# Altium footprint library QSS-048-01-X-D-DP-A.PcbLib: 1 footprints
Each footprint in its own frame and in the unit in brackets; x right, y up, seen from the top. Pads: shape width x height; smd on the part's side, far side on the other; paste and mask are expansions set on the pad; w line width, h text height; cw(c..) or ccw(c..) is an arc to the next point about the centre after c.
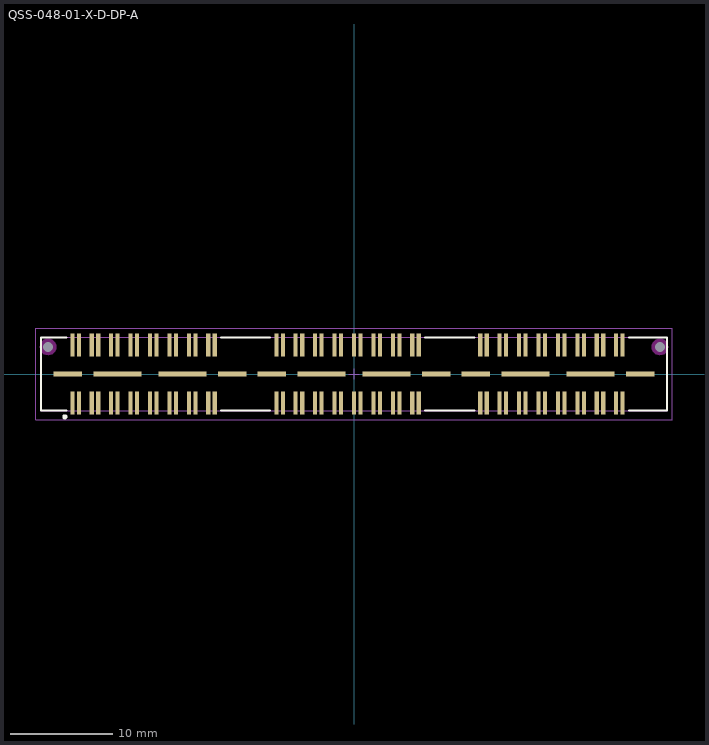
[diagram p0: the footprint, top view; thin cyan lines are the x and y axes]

## QSS-048-01-X-D-DP-A [mm] "0.635mm pitch, high speed socket; differential pair array"
height 3.43
pads (110):
  rect 0.4x2.25 smd mask+0: 1(-27.62,-2.865) 2(-27.62,2.865) 3(-26.98,-2.865) 4(-26.98,2.865) 5(-25.716,-2.865) 6(-25.716,2.865) 7(-25.076,-2.865) 8(-25.076,2.865) 9(-23.812,-2.865) 10(-23.812,2.865) 11(-23.172,-2.865) 12(-23.172,2.865) 13(-21.908,-2.865) 14(-21.908,2.865) 15(-21.268,-2.865) 16(-21.268,2.865) 17(-20.004,-2.865) 18(-20.004,2.865) 19(-19.364,-2.865) 20(-19.364,2.865) 21(-18.1,-2.865) 22(-18.1,2.865) 23(-17.46,-2.865) 24(-17.46,2.865) 25(-16.196,-2.865) 26(-16.196,2.865) 27(-15.556,-2.865) 28(-15.556,2.865) 29(-14.292,-2.865) 30(-14.292,2.865) 31(-13.652,-2.865) 32(-13.652,2.865) 33(-7.62,-2.865) 34(-7.62,2.865) 35(-6.98,-2.865) 36(-6.98,2.865) 37(-5.716,-2.865) 38(-5.716,2.865) 39(-5.076,-2.865) 40(-5.076,2.865) 41(-3.812,-2.865) 42(-3.812,2.865) 43(-3.172,-2.865) 44(-3.172,2.865) 45(-1.908,-2.865) 46(-1.908,2.865) 47(-1.268,-2.865) 48(-1.268,2.865) 49(-0.004,-2.865) 50(-0.004,2.865) 51(0.636,-2.865) 52(0.636,2.865) 53(1.9,-2.865) 54(1.9,2.865) 55(2.54,-2.865) 56(2.54,2.865) 57(3.804,-2.865) 58(3.804,2.865) 59(4.444,-2.865) 60(4.444,2.865) 61(5.708,-2.865) 62(5.708,2.865) 63(6.348,-2.865) 64(6.348,2.865) 65(12.38,-2.865) 66(12.38,2.865) 67(13.02,-2.865) 68(13.02,2.865) 69(14.284,-2.865) 70(14.284,2.865) 71(14.924,-2.865) 72(14.924,2.865) 73(16.188,-2.865) 74(16.188,2.865) 75(16.828,-2.865) 76(16.828,2.865) 77(18.092,-2.865) 78(18.092,2.865) 79(18.732,-2.865) 80(18.732,2.865) 81(19.996,-2.865) 82(19.996,2.865) 83(20.636,-2.865) 84(20.636,2.865) 85(21.9,-2.865) 86(21.9,2.865) 87(22.54,-2.865) 88(22.54,2.865) 89(23.804,-2.865) 90(23.804,2.865) 91(24.444,-2.865) 92(24.444,2.865) 93(25.708,-2.865) 94(25.708,2.865) 95(26.348,-2.865) 96(26.348,2.865)
  rect 2.8x0.45 smd mask+0: 97(-28.065,0) 100(-11.935,0) 101(-8.065,0) 104(8.065,0) 105(11.935,0) 108(28.065,0)
  rect 4.7x0.45 smd mask+0: 98(-23.175,0) 99(-16.825,0) 102(-3.175,0) 103(3.175,0) 106(16.825,0) 107(23.175,0)
  round 0.5 hole 1 unplated mask+0: 109(-30,2.655) 110(30,2.655)
Top Overlay:
  circle w0.25: c-28.35,-4.2 r0.125
  lines w0.2: -28.2,-3.6 -30.7,-3.6 -30.7,3.6 -28.2,3.6 ; -13.05,-3.6 -8.25,-3.6 ; -13.05,3.6 -8.25,3.6 ; 6.95,-3.6 11.8,-3.6 ; 6.95,3.6 11.8,3.6 ; 26.95,-3.6 30.7,-3.6 30.7,3.6 26.95,3.6
Keep-Out Layer:
  pour cut-out: 30.807,2.655 30.779,2.864 30.699,3.058 30.571,3.226 30.403,3.354 30.209,3.434 30,3.462 29.791,3.434 29.597,3.354 29.429,3.226 29.301,3.058 29.221,2.864 29.193,2.655 29.221,2.446 29.301,2.252 29.429,2.084 29.597,1.956 29.791,1.876 30,1.848 30.209,1.876 30.403,1.956 30.571,2.084 30.699,2.252 30.779,2.446
  pour cut-out: -29.193,2.655 -29.221,2.864 -29.301,3.058 -29.429,3.226 -29.597,3.354 -29.791,3.434 -30,3.462 -30.209,3.434 -30.403,3.354 -30.571,3.226 -30.699,3.058 -30.779,2.864 -30.807,2.655 -30.779,2.446 -30.699,2.252 -30.571,2.084 -30.403,1.956 -30.209,1.876 -30,1.848 -29.791,1.876 -29.597,1.956 -29.429,2.084 -29.301,2.252 -29.221,2.446
Mechanical 12:
  lines w0.001: -30.7,-3.6 -30.7,3.6 30.7,3.6 30.7,-3.6 -30.7,-3.6
Mechanical 13:
  lines w0.1: -30.7,-3.6 -30.7,3.6 30.7,3.6 30.7,-3.6 -30.7,-3.6
  text ".Designator" at 0.254,0.254 h1.52
Mechanical 15:
  lines w0.05: -0.5,0 0.5,0 ; 0,-0.5 0,0.5 ; -31.2,-4.5 -31.2,4.5 31.2,4.5 31.2,-4.5 -31.2,-4.5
